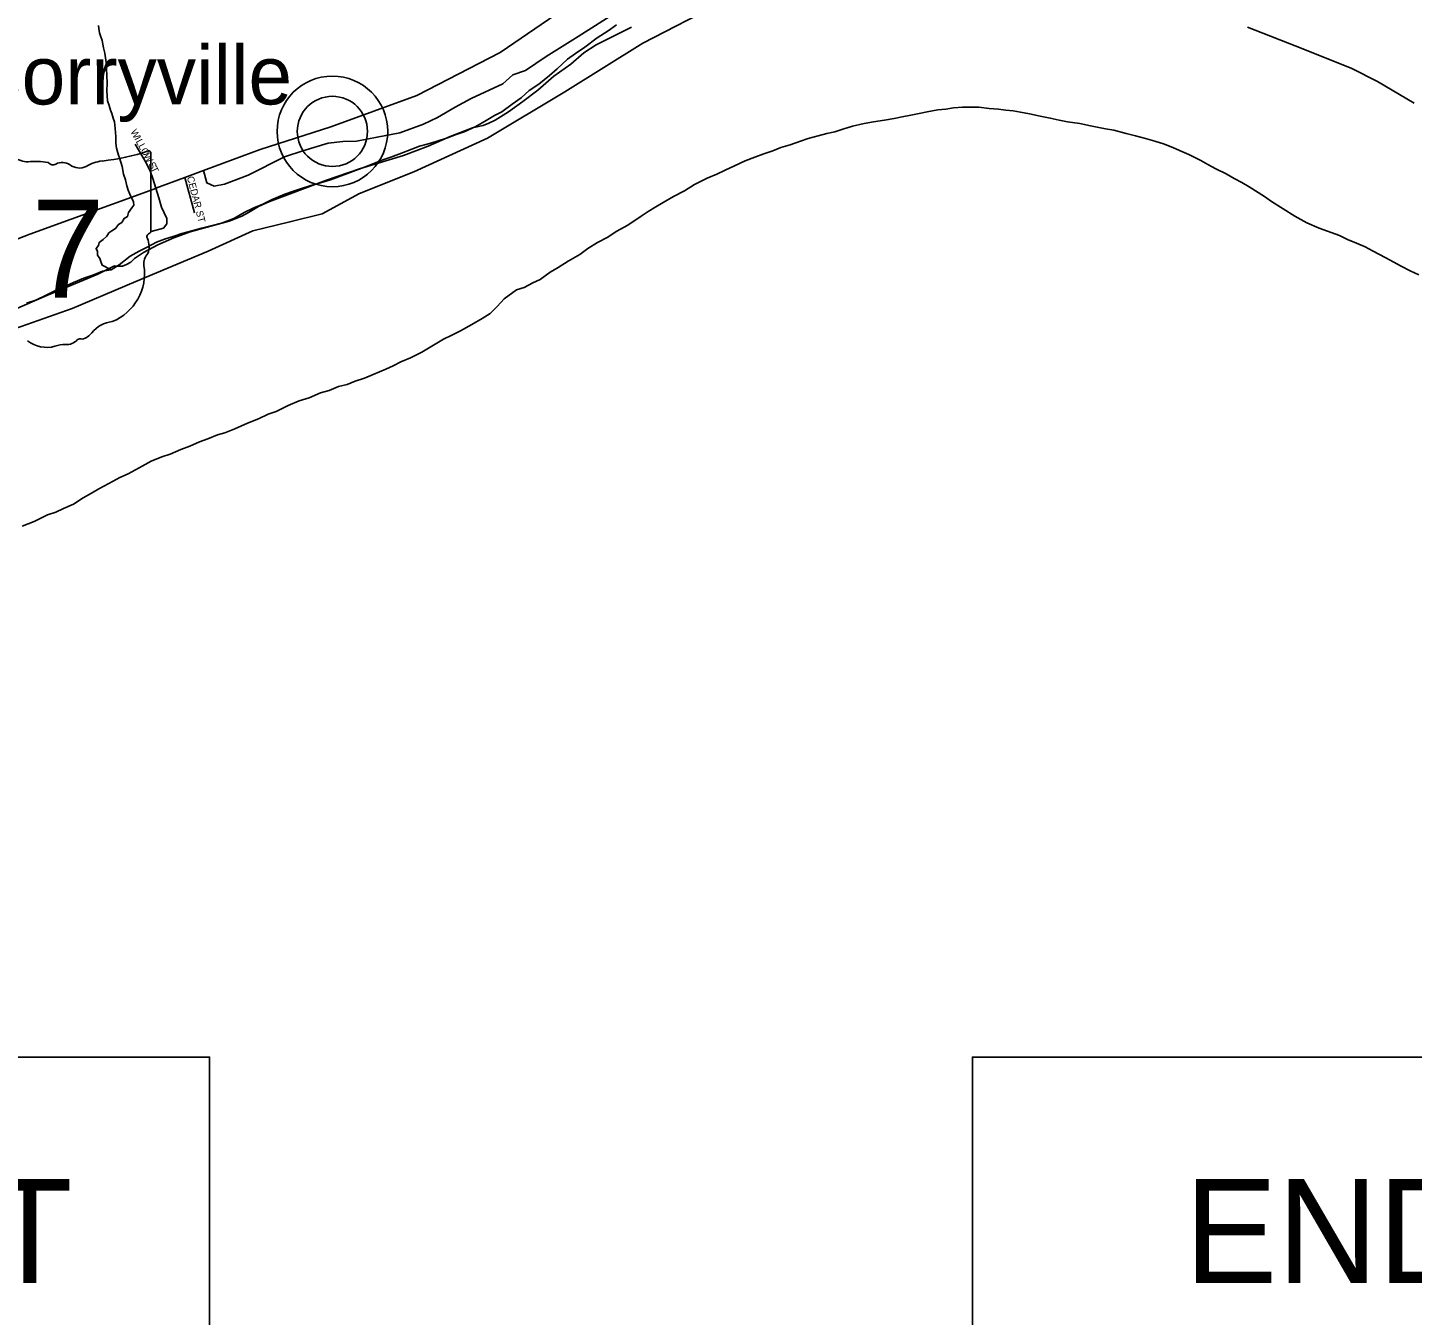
# Model space of a CAD drawing. Extents: x 0 to 34, y 0 to 22.
# Drawn here: x 5.915 to 7.778, y 14.848 to 16.581 of the extents above; entities that cross this region are included whole.
import ezdxf

# ---------------------------------------------------------------- set-up
doc = ezdxf.new("R2010")
doc.units = 0
for name, color, linetype in [('GM_X_County', 7, 'Continuous'), ('GM_X_County_Road', 7, 'Continuous'), ('GM_X_Major_River', 7, 'Continuous'), ('GM_X_Minor_River', 7, 'Continuous'), ('GM_X_Section', 7, 'Continuous'), ('GM_X_State_Location', 7, 'Continuous'), ('GM_X_State_Route', 7, 'Continuous'), ('GM_X_State_Shield', 7, 'Continuous'), ('GM_X_Township', 7, 'Continuous'), ('GM_X_Township_Subdivision', 7, 'Continuous'), ('GM_X_Township_Subdivision_Text', 7, 'Continuous'), ('GM_X_Unincorporated', 7, 'Continuous'), ('GM_X_Unincorporated_Location', 7, 'Continuous'), ('GM_X_Unincorporated_Text', 7, 'Continuous'), ('SH_Text', 7, 'Continuous')]:
    doc.layers.add(name, color=color, linetype=linetype)

msp = doc.modelspace()

# ---------------------------------------------------------------- linework, layer by layer
at = {"layer": 'GM_X_County'}
for points in [[(5.891, 16.1733), (5.9752, 16.2031), (6.0609, 16.2393), (6.158, 16.2801), (6.2179, 16.3076), (6.2679, 16.3195), (6.3115, 16.3302), (6.3616, 16.3576), (6.4344, 16.3867), (6.5337, 16.432), (6.6379, 16.4946), (6.7425, 16.5601), (6.8471, 16.6139)], [(7.5559, 16.5814), (7.6303, 16.5522), (7.6964, 16.5261), (7.7306, 16.5083), (7.78, 16.4795)]]:
    msp.add_lwpolyline(points, dxfattribs=at)
at = {"layer": 'GM_X_County_Road'}
msp.add_lwpolyline([(6.7074, 16.6017), (6.6555, 16.569), (6.6127, 16.542), (6.585, 16.5234), (6.568, 16.5173), (6.5543, 16.5055), (6.5119, 16.4857), (6.4903, 16.4739), (6.4664, 16.4599), (6.4475, 16.4511), (6.4157, 16.4393), (6.3853, 16.4336), (6.3573, 16.4283), (6.3391, 16.4279), (6.3194, 16.4256), (6.2853, 16.4153), (6.2606, 16.407), (6.2118, 16.3826), (6.1799, 16.3704), (6.1659, 16.3674), (6.1564, 16.3719), (6.1519, 16.3886)], dxfattribs=at)
at = {"layer": 'GM_X_Major_River'}
for points in [[(6.7073, 16.5848), (6.6959, 16.5768), (6.6812, 16.5673), (6.6646, 16.5547), (6.6521, 16.5463), (6.6412, 16.5387), (6.6276, 16.5254), (6.617, 16.5166), (6.6027, 16.5048), (6.5898, 16.4964), (6.5792, 16.4865), (6.5671, 16.4781), (6.5532, 16.4674), (6.5433, 16.4625), (6.532, 16.456), (6.518, 16.448), (6.5025, 16.4407), (6.4916, 16.4369), (6.4798, 16.4327), (6.4647, 16.4277), (6.4526, 16.4239), (6.4424, 16.4212), (6.4318, 16.4173), (6.4182, 16.412), (6.4038, 16.4066), (6.3929, 16.4032), (6.3819, 16.3986), (6.3717, 16.3944), (6.3452, 16.3848), (6.3335, 16.3802), (6.3225, 16.376), (6.3093, 16.3722), (6.2961, 16.3687), (6.2824, 16.3642), (6.2715, 16.3603), (6.2609, 16.3569), (6.2439, 16.3496), (6.2314, 16.3435), (6.2193, 16.3385), (6.2065, 16.3321), (6.1925, 16.324), (6.1773, 16.3183), (6.1615, 16.3141), (6.149, 16.311)], [(6.1071, 16.0068), (6.1211, 16.0133), (6.1332, 16.0175), (6.1464, 16.0236), (6.1574, 16.0274), (6.1706, 16.0328), (6.1805, 16.0355), (6.1937, 16.0412), (6.2111, 16.0485), (6.2258, 16.0546), (6.2387, 16.0607), (6.2496, 16.0645), (6.2655, 16.0725), (6.2806, 16.0786), (6.2939, 16.0829), (6.309, 16.0893), (6.3207, 16.0924), (6.3332, 16.0978), (6.3449, 16.1008), (6.3559, 16.1054), (6.3684, 16.1092), (6.3801, 16.1142), (6.3971, 16.1215), (6.4069, 16.126), (6.4171, 16.131), (6.43, 16.1367), (6.4455, 16.1444), (6.4587, 16.1524), (6.4746, 16.1615), (6.4859, 16.1673), (6.4976, 16.173), (6.5128, 16.1814), (6.5267, 16.1894), (6.5373, 16.1963), (6.5468, 16.2058), (6.5562, 16.2161), (6.5728, 16.2279), (6.583, 16.2313), (6.5947, 16.2374), (6.6046, 16.242), (6.6182, 16.2519), (6.6288, 16.258), (6.642, 16.2668), (6.6578, 16.2756), (6.6688, 16.2836), (6.6816, 16.2919), (6.6956, 16.2988), (6.7066, 16.3064), (6.7225, 16.3152), (6.7402, 16.327), (6.75, 16.3335), (6.7602, 16.34), (6.7701, 16.3457), (6.7837, 16.3537), (6.7988, 16.3614), (6.812, 16.3698), (6.829, 16.3785), (6.8422, 16.3839), (6.8536, 16.3892), (6.8661, 16.395), (6.8804, 16.4015), (6.8933, 16.4064), (6.9054, 16.411), (6.9175, 16.4152), (6.9284, 16.4194), (6.9409, 16.4233), (6.9549, 16.4283), (6.9651, 16.4317), (6.9784, 16.4352), (6.9901, 16.4386), (7.0007, 16.4409), (7.0116, 16.4444), (7.0245, 16.4482), (7.0404, 16.452), (7.0529, 16.4543), (7.0676, 16.4563), (7.0805, 16.4586), (7.0915, 16.4609), (7.1032, 16.4632), (7.1145, 16.4655), (7.1251, 16.4675), (7.1395, 16.4702), (7.1501, 16.4713), (7.1607, 16.4732), (7.1728, 16.474), (7.1838, 16.4741), (7.1944, 16.4737), (7.2084, 16.4722), (7.2209, 16.4711), (7.2307, 16.47), (7.2406, 16.4689), (7.2504, 16.467), (7.2625, 16.4648), (7.2769, 16.4618), (7.2906, 16.4592), (7.3027, 16.4565), (7.3137, 16.4543), (7.3303, 16.4517), (7.3447, 16.449), (7.3648, 16.4449), (7.3762, 16.4431)], [(7.3762, 16.4431), (7.3928, 16.4385), (7.4053, 16.4355), (7.4186, 16.4318), (7.4315, 16.428), (7.4444, 16.4239), (7.4565, 16.419), (7.4675, 16.4144), (7.477, 16.4103), (7.4933, 16.4023), (7.5027, 16.3967), (7.5134, 16.391), (7.5274, 16.3842), (7.538, 16.3781), (7.5482, 16.3725), (7.5581, 16.3668), (7.5786, 16.3539), (7.5884, 16.3471), (7.604, 16.3369), (7.6195, 16.3271), (7.6358, 16.3184), (7.6525, 16.3112), (7.6798, 16.3014), (7.6904, 16.2957), (7.7026, 16.2908), (7.7143, 16.2859), (7.7242, 16.2806), (7.742, 16.2712), (7.7518, 16.2659), (7.7628, 16.2598), (7.7746, 16.2538), (7.7863, 16.2481)], [(6.149, 16.311), (6.1361, 16.3076), (6.1225, 16.3037), (6.1123, 16.3003), (6.0994, 16.2964), (6.0885, 16.2922), (6.076, 16.2854), (6.0654, 16.28), (6.0529, 16.2732), (6.0382, 16.2617), (6.0276, 16.2552), (6.0159, 16.2533), (6.0027, 16.248), (5.9906, 16.2438), (5.977, 16.238), (5.9622, 16.2311), (5.9516, 16.2269), (5.9403, 16.2208), (5.9263, 16.2143), (5.9138, 16.2101)], [(5.9079, 15.9099), (5.9241, 15.9163), (5.9419, 15.9251), (5.9532, 15.929), (5.9635, 15.9339), (5.9767, 15.9396), (5.9899, 15.948), (6.0012, 15.9545), (6.0111, 15.9602), (6.0243, 15.9675), (6.039, 15.9755), (6.0504, 15.9805), (6.0651, 15.9885), (6.0814, 15.9976), (6.0957, 16.0034), (6.1071, 16.0068)]]:
    msp.add_lwpolyline(points, dxfattribs=at)
at = {"layer": 'GM_X_Minor_River'}
msp.add_lwpolyline([(6.0276, 16.2552), (6.0152, 16.2611), (6.0134, 16.2664), (6.0123, 16.2703), (6.0093, 16.2749), (6.009, 16.2798), (6.0072, 16.2837), (6.0107, 16.2878), (6.0115, 16.2919), (6.0169, 16.296), (6.0219, 16.3001), (6.0246, 16.3047), (6.0285, 16.3073), (6.0334, 16.3106), (6.0373, 16.3162), (6.0419, 16.3188), (6.045, 16.3241), (6.0493, 16.3267), (6.0509, 16.3323), (6.0555, 16.3384), (6.0582, 16.3421), (6.0576, 16.3467), (6.0528, 16.3567), (6.0506, 16.362), (6.0485, 16.3681), (6.0467, 16.3762), (6.0442, 16.3838), (6.0425, 16.3941), (6.0389, 16.4056), (6.0374, 16.4094), (6.0349, 16.4189), (6.0339, 16.4254), (6.0336, 16.4296), (6.0337, 16.4346), (6.0331, 16.4452), (6.0318, 16.454), (6.03, 16.4593), (6.0282, 16.4655), (6.0264, 16.4697), (6.025, 16.4762), (6.0228, 16.4823), (6.0221, 16.4891), (6.0219, 16.496), (6.0221, 16.5059), (6.0219, 16.5169), (6.0213, 16.5249), (6.0207, 16.534), (6.02, 16.5405), (6.019, 16.5466), (6.0172, 16.5539), (6.0155, 16.5638), (6.0133, 16.5699), (6.0119, 16.5741), (6.0108, 16.5798), (6.0105, 16.5836)], dxfattribs=at)
at = {"layer": 'GM_X_Section'}
msp.add_lwpolyline([(6.7273, 16.5816), (6.68, 16.5577), (6.6633, 16.5471), (6.6459, 16.5319), (6.6228, 16.5156), (6.6012, 16.4967), (6.5811, 16.4815), (6.5618, 16.4678), (6.544, 16.4565), (6.5353, 16.4523), (6.5281, 16.4493), (6.5194, 16.4474), (6.5137, 16.4462), (6.4834, 16.4344), (6.4539, 16.4212), (6.4209, 16.409), (6.363, 16.3915), (6.3171, 16.3756), (6.2395, 16.3467), (6.2258, 16.3403), (6.2122, 16.3323), (6.2031, 16.3274), (6.1861, 16.3206), (6.1565, 16.3122), (6.1338, 16.3061), (6.1118, 16.2981), (6.0902, 16.2887), (6.0709, 16.2784), (6.0588, 16.2704), (6.0539, 16.2655), (6.0482, 16.2621), (6.0429, 16.2598), (6.0361, 16.2598), (6.0319, 16.2606), (6.0095, 16.2492), (5.941, 16.2203), (5.8974, 16.2017)], dxfattribs=at)
at = {"layer": 'GM_X_State_Route'}
for points in [[(6.1519, 16.3886), (6.1796, 16.3989), (6.2278, 16.4168), (6.3229, 16.4476), (6.4385, 16.4897), (6.5509, 16.5474), (6.6523, 16.6172), (6.7498, 16.6817), (6.8399, 16.7419), (6.9637, 16.8138), (7.0899, 16.8914), (7.1864, 16.9474)], [(5.675, 16.2138), (5.6858, 16.2175), (5.6895, 16.2188), (5.7046, 16.2241), (5.8127, 16.2622), (5.9183, 16.303), (6.0847, 16.3636), (6.0876, 16.3647), (6.1268, 16.3793), (6.1519, 16.3886)]]:
    msp.add_lwpolyline(points, dxfattribs=at)
at = {"layer": 'GM_X_State_Shield'}
for q in [(6.0808, 16.4118), (6.0808, 16.3071)]:
    msp.add_line((6.0808, 16.3071), q, dxfattribs=at)
for centre, radius, start, end in [((5.9869, 16.6796), 0.2796, 275.8445, 288.9065), ((6.0779, 16.4122), 0.00294, 351.8621, 97.738), ((5.9153, 16.43), 0.0296, 231.6195, 271.1119), ((5.9251, 16.2945), 0.1064, 80.4867, 94.9883), ((5.9493, 16.4048), 0.00855, 219.7921, 297.1024), ((5.9618, 16.3817), 0.0178, 54.4667, 119.1411), ((5.9848, 16.4134), 0.0214, 233.8562, 294.8282), ((6.0225, 16.3457), 0.0563, 97.3462, 120.7689), ((6.0801, 16.2994), 0.00454, 107.944, 210.337), ((6.0512, 16.2862), 0.0273, 340.033, 23.6496), ((6.0777, 16.3067), 0.00314, 289.6038, 7.7341), ((6.0025, 16.25), 0.0699, 292.3089, 8.9858), ((6.0913, 16.2633), 0.0198, 136.8065, 186.9296), ((6.032, 16.1471), 0.0383, 94.4031, 142.5768), ((5.9835, 16.1838), 0.0226, 282.8732, 323.2771), ((5.9406, 16.1907), 0.0401, 230.7004, 286.2918), ((5.9638, 16.1215), 0.0329, 85.6951, 111.2099), ((5.9667, 16.1757), 0.0214, 268.777, 315.5493), ((5.986, 16.1563), 0.00601, 65.7517, 132.6484)]:
    msp.add_arc(centre, radius, start, end, dxfattribs=at)
at = {"layer": 'GM_X_Township'}
for points in [[(5.891, 16.1733), (5.9752, 16.2031), (6.0609, 16.2393), (6.158, 16.2801), (6.2179, 16.3076), (6.2679, 16.3195), (6.3115, 16.3302), (6.3616, 16.3576), (6.4344, 16.3867), (6.5337, 16.432), (6.6379, 16.4946), (6.7425, 16.5601), (6.8471, 16.6139)], [(7.5559, 16.5814), (7.6303, 16.5522), (7.6964, 16.5261), (7.7306, 16.5083), (7.78, 16.4795)]]:
    msp.add_lwpolyline(points, dxfattribs=at)
at = {"layer": 'GM_X_Township_Subdivision'}
for points in [[(6.0834, 16.378), (6.0806, 16.387), (6.0746, 16.3988), (6.0598, 16.4239)], [(6.0814, 16.3068), (6.0977, 16.311), (6.1022, 16.3167), (6.1026, 16.3243), (6.0954, 16.3395), (6.0916, 16.3517), (6.0876, 16.3647), (6.0834, 16.378)], [(6.1268, 16.3793), (6.1394, 16.3317)]]:
    msp.add_lwpolyline(points, dxfattribs=at)
at = {"layer": 'GM_X_Unincorporated'}
for radius in [0.0744, 0.0472]:
    msp.add_circle((6.3251, 16.4413), radius, dxfattribs=at)
at = {"layer": 'GM_X_Unincorporated_Location'}
msp.add_line((6.3251, 16.4413), (6.3251, 16.4413), dxfattribs=at)
at = {"layer": 'SH_Text'}
for points in [[(4.3169, 15.1955), (6.1599, 15.1955), (6.1599, 14.3684), (4.3169, 14.3684)], [(9.029, 15.1955), (7.186, 15.1955), (7.186, 14.3684), (9.029, 14.3684)]]:
    msp.add_lwpolyline(points, close=True, dxfattribs=at)

# ---------------------------------------------------------------- texts
at = {"layer": 'GM_X_State_Location'}
for s in ['s', 'r']:
    msp.add_text(s, height=0.000189, dxfattribs=at).set_placement((5.946, 16.29))
msp.add_text('7', height=0.000189, rotation=0, dxfattribs=at).set_placement((5.9175, 16.2762))
at = {"layer": 'GM_X_State_Shield'}
msp.add_text('7', height=0.1318, dxfattribs=at).set_placement((5.9205, 16.2174))
at = {"layer": 'GM_X_Township_Subdivision_Text'}
for s, rotation, p in [('W', 298.5165, (6.0532, 16.441)), ('I', 298.4916, (6.0584, 16.4314)), ('L', 298.5251, (6.0603, 16.4278)), ('L', 298.5255, (6.0635, 16.4219)), ('O', 298.5263, (6.0667, 16.4161)), ('W', 298.5155, (6.0707, 16.4087)), ('S', 298.5251, (6.0771, 16.397)), ('T', 295.4418, (6.0802, 16.3913)), ('CEDAR ST', 284.6585, (6.1292, 16.3797))]:
    msp.add_text(s, height=0.00947, rotation=rotation, dxfattribs=at).set_placement(p)
at = {"layer": 'GM_X_Unincorporated_Text'}
msp.add_text('Corryville', height=0.07898, rotation=0, dxfattribs=at).set_placement((5.8308, 16.4776))
at = {"layer": 'SH_Text'}
for s, p in [('BEGIN PROJECT', (4.4671, 14.8915)), ('END PROJECT', (7.4713, 14.8915))]:
    msp.add_text(s, height=0.14, dxfattribs=at).set_placement(p)

doc.saveas('drawing.dxf')
